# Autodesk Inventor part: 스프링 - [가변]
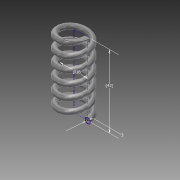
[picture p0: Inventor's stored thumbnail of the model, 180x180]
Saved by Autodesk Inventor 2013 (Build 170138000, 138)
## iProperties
Created: 2015-12
Part Number: 스프링 - [가변]
Material: 강철, 탄소
Document SubType Name: Modeling
Designer: Administrator
Density: 7.87 g/cm^3
Mass: 16.5219 g
Surface Area: 28.4696 cm^2
Volume: 2.09936 cm^3
Author: Administrator
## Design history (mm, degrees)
sketch "스케치1"
  geometry: L1 (0, 0)-(-8, 0); L2 (-8, 0)-(-8, 42); L3 (-8, 42)-(0, 42); L4 (0, 42)-(0, 0); C1 r 1.5 at (-8, 0)
  constraints: 8 end point, 2 parallel, 1 centre point, 1 coincident, 1 horizontal, 1 perpendicular
  dimensions: "d0" = 3 diameter of C1; "d2" = 42 distance of L1.end L2.end (derived); "d3" = 16 diameter of L2 L4
feature "코일1" pitch "d4" = 10; turns "d6" = 6; dims "d5" = 42 (= d2), "d7" = 0, angle "d8" = 90 deg, angle "d9" = 90 deg, "d10" = 0, "d11" = 0
sketch "스케치2"
  geometry: L1 (9.5, 0)-(6.5, 0) reference; 1 further point
  constraints: 1 horizontal alignment
extrude "돌출1" cut sketch "스케치2" distance "d12" = 10; taper "d13" = 0 deg
node "작업 평면1"
sketch "스케치3"
  geometry: L1 (-1.5, 0)-(1.5, 0) reference; 1 further point
  constraints: 1 horizontal alignment
extrude "돌출2" cut sketch "스케치3" distance "d15" = 10; taper "d16" = 0 deg
node "솔리드1"
node "절단 모서리 투영1"
node "절단 모서리 투영2"
other parameters: "d14" = 90 deg
